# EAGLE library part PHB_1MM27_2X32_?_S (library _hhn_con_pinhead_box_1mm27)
Pin Header Box-Type, 1.27mm/0.5"/50mil Pitch, 2x32 Circuits, single gates in schematic Note: see library description for an important note about THT-version
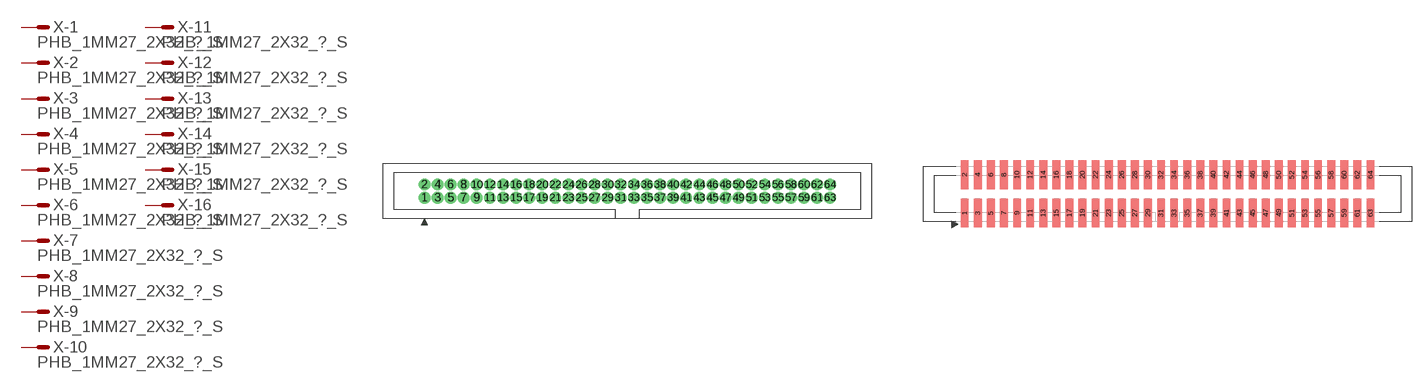
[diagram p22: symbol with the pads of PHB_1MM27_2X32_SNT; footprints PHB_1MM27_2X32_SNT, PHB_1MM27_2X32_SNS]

Designator prefix X; gates -1=M -2=M -3=M -4=M -5=M -6=M -7=M -8=M -9=M -10=M -11=M -12=M -13=M -14=M -15=M -16=M -17=M -18=M -19=M -20=M -21=M -22=M -23=M -24=M -25=M -26=M -27=M -28=M -29=M -30=M -31=M -32=M -33=M -34=M -35=M -36=M -37=M -38=M -39=M -40=M -41=M -42=M -43=M -44=M -45=M -46=M -47=M -48=M -49=M -50=M -51=M -52=M -53=M -54=M -55=M -56=M -57=M -58=M -59=M -60=M -61=M -62=M -63=M -64=M

## PHB_1MM27_2X32_SNT_S  [PHB_1MM27_2X32_SNT]
1  -1:S  pas
2  -2:S  pas
3  -3:S  pas
4  -4:S  pas
5  -5:S  pas
6  -6:S  pas
7  -7:S  pas
8  -8:S  pas
9  -9:S  pas
10  -10:S  pas
11  -11:S  pas
12  -12:S  pas
13  -13:S  pas
14  -14:S  pas
15  -15:S  pas
16  -16:S  pas
17  -17:S  pas
18  -18:S  pas
19  -19:S  pas
20  -20:S  pas
21  -21:S  pas
22  -22:S  pas
23  -23:S  pas
24  -24:S  pas
25  -25:S  pas
26  -26:S  pas
27  -27:S  pas
28  -28:S  pas
29  -29:S  pas
30  -30:S  pas
31  -31:S  pas
32  -32:S  pas
33  -33:S  pas
34  -34:S  pas
35  -35:S  pas
36  -36:S  pas
37  -37:S  pas
38  -38:S  pas
39  -39:S  pas
40  -40:S  pas
41  -41:S  pas
42  -42:S  pas
43  -43:S  pas
44  -44:S  pas
45  -45:S  pas
46  -46:S  pas
47  -47:S  pas
48  -48:S  pas
49  -49:S  pas
50  -50:S  pas
51  -51:S  pas
52  -52:S  pas
53  -53:S  pas
54  -54:S  pas
55  -55:S  pas
56  -56:S  pas
57  -57:S  pas
58  -58:S  pas
59  -59:S  pas
60  -60:S  pas
61  -61:S  pas
62  -62:S  pas
63  -63:S  pas
64  -64:S  pas

## PHB_1MM27_2X32_SNS_S  [PHB_1MM27_2X32_SNS]
Pads as for PHB_1MM27_2X32_SNT

## Footprint PHB_1MM27_2X32_SNT (pad centres in mm)
Pin Header Box-Type, 1.27mm Pitch, 2x32 circuits, Straight, No Locking, THT Important Note: Diameter in this lbr is set to a specific value (NOT 'auto' = 0), this is ignored by actual eagle versions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
drill 0.65 pad 1 round: 1 -19.685,-0.635; 2 -19.685,0.635; 3 -18.415,-0.635; 4 -18.415,0.635; 5 -17.145,-0.635; 6 -17.145,0.635; 7 -15.875,-0.635; 8 -15.875,0.635; 9 -14.605,-0.635; 10 -14.605,0.635; 11 -13.335,-0.635; 12 -13.335,0.635; 13 -12.065,-0.635; 14 -12.065,0.635; 15 -10.795,-0.635; 16 -10.795,0.635; 17 -9.525,-0.635; 18 -9.525,0.635; 19 -8.255,-0.635; 20 -8.255,0.635; 21 -6.985,-0.635; 22 -6.985,0.635; 23 -5.715,-0.635; 24 -5.715,0.635; 25 -4.445,-0.635; 26 -4.445,0.635; 27 -3.175,-0.635; 28 -3.175,0.635; 29 -1.905,-0.635; 30 -1.905,0.635; 31 -0.635,-0.635; 32 -0.635,0.635; 33 0.635,-0.635; 34 0.635,0.635; 35 1.905,-0.635; 36 1.905,0.635; 37 3.175,-0.635; 38 3.175,0.635; 39 4.445,-0.635; 40 4.445,0.635; 41 5.715,-0.635; 42 5.715,0.635; 43 6.985,-0.635; 44 6.985,0.635; 45 8.255,-0.635; 46 8.255,0.635; 47 9.525,-0.635; 48 9.525,0.635; 49 10.795,-0.635; 50 10.795,0.635; 51 12.065,-0.635; 52 12.065,0.635; 53 13.335,-0.635; 54 13.335,0.635; 55 14.605,-0.635; 56 14.605,0.635; 57 15.875,-0.635; 58 15.875,0.635; 59 17.145,-0.635; 60 17.145,0.635; 61 18.415,-0.635; 62 18.415,0.635; 63 19.685,-0.635; 64 19.685,0.635

## Footprint PHB_1MM27_2X32_SNS (pad centres in mm)
Pin Header Box-Type, 1.27mm Pitch, 2x32 circuits, Straight, No Locking, SMT
smd 0.76 x 2.8: 1 -19.685,-1.85; 2 -19.685,1.85; 3 -18.415,-1.85; 4 -18.415,1.85; 5 -17.145,-1.85; 6 -17.145,1.85; 7 -15.875,-1.85; 8 -15.875,1.85; 9 -14.605,-1.85; 10 -14.605,1.85; 11 -13.335,-1.85; 12 -13.335,1.85; 13 -12.065,-1.85; 14 -12.065,1.85; 15 -10.795,-1.85; 16 -10.795,1.85; 17 -9.525,-1.85; 18 -9.525,1.85; 19 -8.255,-1.85; 20 -8.255,1.85; 21 -6.985,-1.85; 22 -6.985,1.85; 23 -5.715,-1.85; 24 -5.715,1.85; 25 -4.445,-1.85; 26 -4.445,1.85; 27 -3.175,-1.85; 28 -3.175,1.85; 29 -1.905,-1.85; 30 -1.905,1.85; 31 -0.635,-1.85; 32 -0.635,1.85; 33 0.635,-1.85; 34 0.635,1.85; 35 1.905,-1.85; 36 1.905,1.85; 37 3.175,-1.85; 38 3.175,1.85; 39 4.445,-1.85; 40 4.445,1.85; 41 5.715,-1.85; 42 5.715,1.85; 43 6.985,-1.85; 44 6.985,1.85; 45 8.255,-1.85; 46 8.255,1.85; 47 9.525,-1.85; 48 9.525,1.85; 49 10.795,-1.85; 50 10.795,1.85; 51 12.065,-1.85; 52 12.065,1.85; 53 13.335,-1.85; 54 13.335,1.85; 55 14.605,-1.85; 56 14.605,1.85; 57 15.875,-1.85; 58 15.875,1.85; 59 17.145,-1.85; 60 17.145,1.85; 61 18.415,-1.85; 62 18.415,1.85; 63 19.685,-1.85; 64 19.685,1.85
